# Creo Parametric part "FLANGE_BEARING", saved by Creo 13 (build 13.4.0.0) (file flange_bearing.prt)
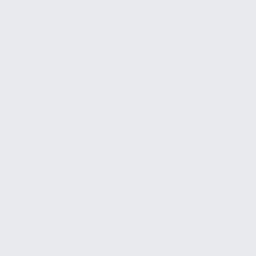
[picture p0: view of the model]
Units: millimeter Newton Second (mmNs); MM, TONNE, SECS

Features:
  1. datum plane "RIGHT"
  2. datum plane "TOP"
  3. datum plane "FRONT"
  4. coordinate system
  5. protrusion
  6. protrusion
  7. cut
  8. cut
  9. round

Surfaces: 10 cylinder, 7 plane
